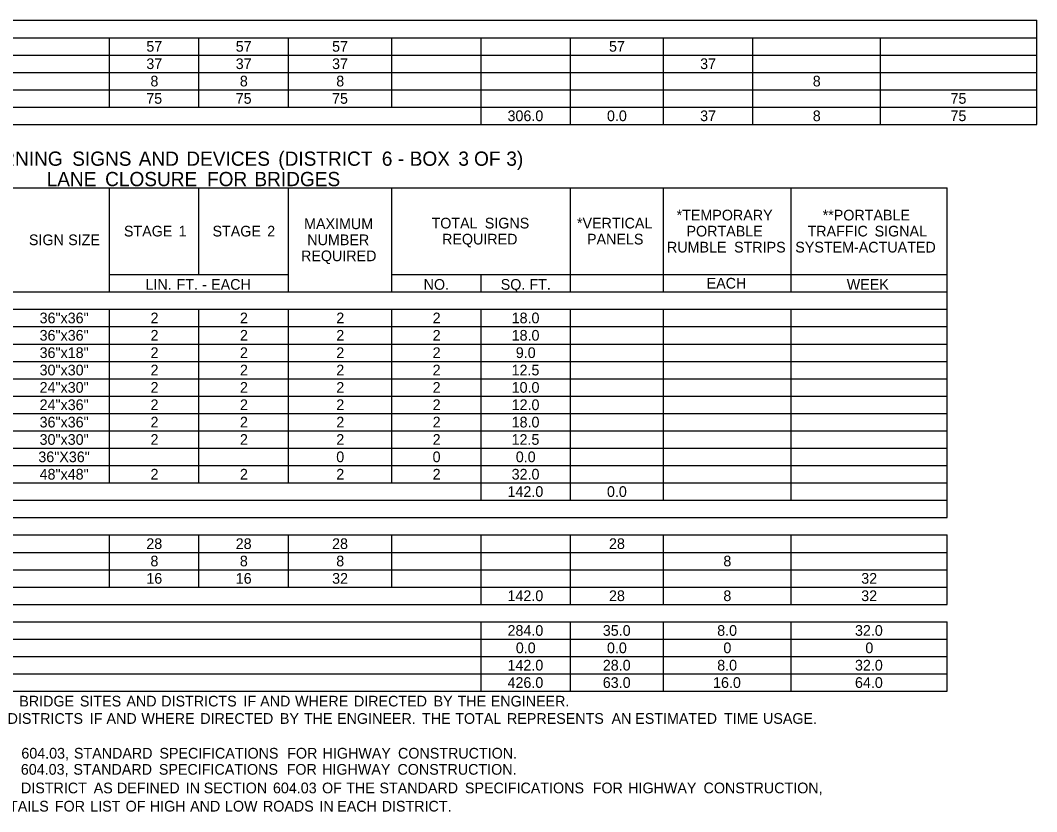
# Model space of a CAD drawing. Extents: x 542596 to 1930787, y -1948294 to 596640.
# Drawn here: x 542920 to 543491, y -1946974 to -1946530 of the extents above; entities that cross this region are included whole.
import ezdxf

# ---------------------------------------------------------------- set-up
doc = ezdxf.new("R2010")
doc.units = 0
doc.layers.add('Default', color=7, linetype='Continuous')

msp = doc.modelspace()

# ---------------------------------------------------------------- linework, layer by layer
at = {"layer": 'Default'}
for p, q in [((542602.25, -1946529.94), (543490.96, -1946529.94)), ((542652.46, -1946529.94), (543403.21, -1946529.94)), ((543403.21, -1946529.94), (543490.96, -1946529.94)), ((543490.96, -1946588.44), (543490.96, -1946529.94)), ((542602.25, -1946539.69), (543490.96, -1946539.69)), ((542970.31, -1946578.69), (542970.31, -1946539.69)), ((542970.31, -1946578.69), (542970.31, -1946539.69)), ((543020.52, -1946578.69), (543020.52, -1946539.69)), ((543020.52, -1946578.69), (543020.52, -1946539.69)), ((543070.73, -1946578.69), (543070.73, -1946539.69)), ((543070.73, -1946578.69), (543070.73, -1946539.69)), ((543128.75, -1946578.69), (543128.75, -1946539.69)), ((543178.96, -1946578.69), (543178.96, -1946539.69)), ((543178.96, -1946588.44), (543178.96, -1946539.69)), ((543229.17, -1946588.44), (543229.17, -1946539.69)), ((543229.17, -1946588.44), (543229.17, -1946539.69)), ((543281.33, -1946588.44), (543281.33, -1946539.69)), ((543281.33, -1946588.44), (543281.33, -1946539.69)), ((543331.55, -1946588.44), (543331.55, -1946539.69)), ((543331.55, -1946588.44), (543331.55, -1946539.69)), ((543403.21, -1946588.44), (543403.21, -1946539.69)), ((542602.25, -1946549.44), (543490.96, -1946549.44)), ((542602.25, -1946559.19), (543490.96, -1946559.19)), ((542602.25, -1946568.94), (543490.96, -1946568.94)), ((542602.25, -1946578.69), (543490.96, -1946578.69)), ((542920.1, -1946578.69), (543178.96, -1946578.69)), ((543403.21, -1946588.44), (543403.21, -1946578.69)), ((542602.25, -1946588.44), (543490.96, -1946588.44)), ((542602.25, -1946623.95), (543440.75, -1946623.95)), ((542970.31, -1946682.45), (542970.31, -1946623.95)), ((543020.52, -1946672.7), (543020.52, -1946623.95)), ((543070.73, -1946682.45), (543070.73, -1946623.95)), ((543128.75, -1946682.45), (543128.75, -1946623.95)), ((543229.17, -1946682.45), (543229.17, -1946623.95)), ((543281.33, -1946682.45), (543281.33, -1946623.95)), ((543353, -1946682.45), (543353, -1946623.95)), ((543440.75, -1946809.2), (543440.75, -1946623.95)), ((542970.31, -1946672.7), (543070.73, -1946672.7)), ((543070.73, -1946682.45), (543070.73, -1946672.7)), ((543128.75, -1946672.7), (543440.75, -1946672.7)), ((543178.96, -1946682.45), (543178.96, -1946672.7)), ((543229.17, -1946682.45), (543229.17, -1946672.7)), ((543281.33, -1946682.45), (543281.33, -1946672.7)), ((543353, -1946682.45), (543353, -1946672.7)), ((542602.25, -1946682.45), (543440.75, -1946682.45)), ((543070.73, -1946682.45), (543229.17, -1946682.45)), ((543229.17, -1946682.45), (543281.33, -1946682.45)), ((543281.33, -1946682.45), (543440.75, -1946682.45)), ((542602.25, -1946692.2), (543440.75, -1946692.2)), ((542970.31, -1946789.7), (542970.31, -1946692.2)), ((542970.31, -1946789.7), (542970.31, -1946692.2)), ((543020.52, -1946779.95), (543020.52, -1946692.2)), ((543020.52, -1946789.7), (543020.52, -1946692.2)), ((543070.73, -1946789.7), (543070.73, -1946692.2)), ((543070.73, -1946789.7), (543070.73, -1946692.2)), ((543128.75, -1946789.7), (543128.75, -1946692.2)), ((543178.96, -1946789.7), (543178.96, -1946692.2)), ((543178.96, -1946799.45), (543178.96, -1946692.2)), ((543229.17, -1946779.95), (543229.17, -1946692.2)), ((543229.17, -1946799.45), (543229.17, -1946692.2)), ((543281.33, -1946740.95), (543281.33, -1946692.2)), ((543281.33, -1946799.45), (543281.33, -1946692.2)), ((543353, -1946799.45), (543353, -1946692.2)), ((542602.25, -1946701.95), (543440.75, -1946701.95)), ((542602.25, -1946711.7), (543440.75, -1946711.7)), ((542602.25, -1946721.45), (543440.75, -1946721.45)), ((542602.25, -1946731.2), (543440.75, -1946731.2)), ((542602.25, -1946740.95), (543440.75, -1946740.95)), ((542602.25, -1946750.7), (543440.75, -1946750.7)), ((543281.33, -1946799.45), (543281.33, -1946750.7)), ((542602.25, -1946760.45), (543440.75, -1946760.45)), ((542602.25, -1946770.2), (543440.75, -1946770.2)), ((542602.25, -1946779.95), (543440.75, -1946779.95)), ((542602.25, -1946789.7), (543440.75, -1946789.7)), ((543178.96, -1946789.7), (543440.75, -1946789.7)), ((543353, -1946799.45), (543353, -1946789.7)), ((542602.25, -1946799.45), (543440.75, -1946799.45)), ((543353, -1946799.45), (543440.75, -1946799.45)), ((542602.25, -1946809.2), (543440.75, -1946809.2)), ((542652.46, -1946809.2), (543353, -1946809.2)), ((543353, -1946809.2), (543440.75, -1946809.2)), ((542602.25, -1946818.95), (543440.75, -1946818.95)), ((542970.31, -1946848.2), (542970.31, -1946818.95)), ((542970.31, -1946848.2), (542970.31, -1946818.95)), ((543020.52, -1946848.2), (543020.52, -1946818.95)), ((543020.52, -1946848.2), (543020.52, -1946818.95)), ((543070.73, -1946848.2), (543070.73, -1946818.95)), ((543070.73, -1946848.2), (543070.73, -1946818.95)), ((543128.75, -1946848.2), (543128.75, -1946818.95)), ((543178.96, -1946848.2), (543178.96, -1946818.95)), ((543178.96, -1946857.95), (543178.96, -1946818.95)), ((543229.17, -1946857.95), (543229.17, -1946818.95)), ((543229.17, -1946857.95), (543229.17, -1946818.95)), ((543281.33, -1946857.95), (543281.33, -1946818.95)), ((543281.33, -1946857.95), (543281.33, -1946818.95)), ((543353, -1946857.95), (543353, -1946818.95)), ((543440.75, -1946857.95), (543440.75, -1946818.95)), ((542602.25, -1946828.7), (543440.75, -1946828.7)), ((543353, -1946838.45), (543353, -1946828.7)), ((542602.25, -1946838.45), (543440.75, -1946838.45)), ((542602.25, -1946848.2), (543440.75, -1946848.2)), ((542602.25, -1946848.2), (543440.75, -1946848.2)), ((543353, -1946857.95), (543353, -1946848.2)), ((542602.25, -1946857.95), (543440.75, -1946857.95)), ((542602.25, -1946867.7), (543440.75, -1946867.7)), ((543178.96, -1946906.7), (543178.96, -1946867.7)), ((543178.96, -1946906.7), (543178.96, -1946867.7)), ((543229.17, -1946906.7), (543229.17, -1946867.7)), ((543281.33, -1946906.7), (543281.33, -1946867.7)), ((543353, -1946906.7), (543353, -1946867.7)), ((543440.75, -1946906.7), (543440.75, -1946867.7)), ((542602.25, -1946877.45), (543440.75, -1946877.45)), ((542602.25, -1946887.2), (543440.75, -1946887.2)), ((542602.25, -1946896.95), (543440.75, -1946896.95)), ((542602.25, -1946906.7), (543440.75, -1946906.7))]:
    msp.add_line(p, q, dxfattribs=at)

# ---------------------------------------------------------------- texts
for s, height, p in [('57', 6, (542990.95, -1946547.56)), ('57', 6, (543041.16, -1946547.56)), ('57', 6, (543095.27, -1946547.56)), ('57', 6, (543250.78, -1946547.56)), ('37', 6, (542990.95, -1946557.31)), ('37', 6, (543041.16, -1946557.31)), ('37', 6, (543095.27, -1946557.31)), ('37', 6, (543301.97, -1946557.31)), ('8', 6, (542993.27, -1946567.06)), ('8', 6, (543043.48, -1946567.06)), ('8', 6, (543097.6, -1946567.06)), ('8', 6, (543365.23, -1946567.06)), ('75', 6, (542990.92, -1946576.81)), ('75', 6, (543041.14, -1946576.81)), ('75', 6, (543095.25, -1946576.81)), ('75', 6, (543442.59, -1946576.81)), ('306.0', 6, (543193.79, -1946586.56)), ('0.0', 6, (543249.64, -1946586.56)), ('37', 6, (543301.97, -1946586.56)), ('8', 6, (543365.24, -1946586.56)), ('75', 6, (543442.55, -1946586.56)), (' WARNING', 8, (542889.27, -1946611.62)), (' SIGNS', 8, (542946.34, -1946611.62)), (' AND', 8, (542983.68, -1946611.62)), (' DEVICES', 8, (543010.45, -1946611.62)), (' (DISTRICT', 8, (543062.08, -1946611.62)), (' 6', 8, (543120.22, -1946611.62)), (' -', 8, (543129.14, -1946611.62)), (' BOX', 8, (543135.88, -1946611.62)), (' 3', 8, (543163.2, -1946611.62)), (' OF', 8, (543172.03, -1946611.62)), (' 3)', 8, (543190.14, -1946611.62)), ('LANE', 8, (542934.96, -1946623.07)), (' CLOSURE', 8, (542964.84, -1946623.07)), (' FOR', 8, (543022.05, -1946623.07)), (' BRIDGES', 8, (543048.69, -1946623.07)), ('*TEMPORARY', 6, (543288.74, -1946642.32)), ('**PORTABLE', 6, (543370.76, -1946642.32)), ('MAXIMUM', 6, (543079.55, -1946647.2)), ('TOTAL', 6, (543151.11, -1946646.82)), (' SIGNS', 6, (543178.8, -1946646.82)), ('*VERTICAL', 6, (543232.79, -1946646.82)), ('STAGE', 6, (542978.37, -1946651.32)), (' 1', 6, (543006.84, -1946651.32)), ('STAGE', 6, (543028.11, -1946651.32)), (' 2', 6, (543056.58, -1946651.32)), ('PORTABLE', 6, (543294.32, -1946651.32)), ('TRAFFIC', 6, (543362.28, -1946651.32)), (' SIGNAL', 6, (543397.71, -1946651.32)), ('SIGN', 6, (542925.02, -1946656.2)), (' SIZE', 6, (542944.84, -1946656.2)), ('NUMBER', 6, (543081.36, -1946656.2)), ('REQUIRED', 6, (543157.04, -1946655.82)), ('PANELS', 6, (543238.45, -1946655.82)), ('REQUIRED', 6, (543077.82, -1946665.2)), ('RUMBLE', 6, (543283.34, -1946660.32)), (' STRIPS', 6, (543318.79, -1946660.32)), ('SYSTEM-ACTUATED', 6, (543355.39, -1946660.32)), ('LIN.', 6, (542990.48, -1946681.25)), (' FT.', 6, (543005.74, -1946681.25)), (' EACH', 6, (543025.12, -1946681.25)), ('NO.', 6, (543146.69, -1946681.25)), ('SQ.', 6, (543189.97, -1946681.25)), (' FT.', 6, (543203.84, -1946681.25)), ('EACH', 6, (543305.61, -1946680.57)), ('WEEK', 6, (543384.3, -1946681.25)), (' -', 6, (543020.06, -1946681.25)), ('36"x36"', 6, (542931.01, -1946700.07)), ('2', 6, (542993.31, -1946700.07)), ('2', 6, (543043.52, -1946700.07)), ('2', 6, (543097.63, -1946700.07)), ('2', 6, (543151.75, -1946700.07)), ('18.0', 6, (543196.11, -1946700.07)), ('36"x36"', 6, (542931.01, -1946709.82)), ('2', 6, (542993.31, -1946709.82)), ('2', 6, (543043.52, -1946709.82)), ('2', 6, (543097.63, -1946709.82)), ('2', 6, (543151.75, -1946709.82)), ('18.0', 6, (543196.11, -1946709.82)), ('36"x18"', 6, (542931.01, -1946719.57)), ('2', 6, (542993.31, -1946719.57)), ('2', 6, (543043.52, -1946719.57)), ('2', 6, (543097.63, -1946719.57)), ('2', 6, (543151.75, -1946719.57)), ('9.0', 6, (543198.44, -1946719.57)), ('30"x30"', 6, (542931.01, -1946729.32)), ('2', 6, (542993.31, -1946729.32)), ('2', 6, (543043.52, -1946729.32)), ('2', 6, (543097.63, -1946729.32)), ('2', 6, (543151.75, -1946729.32)), ('12.5', 6, (543196.08, -1946729.32)), ('24"x30"', 6, (542931.01, -1946739.07)), ('2', 6, (542993.31, -1946739.07)), ('2', 6, (543043.52, -1946739.07)), ('2', 6, (543097.63, -1946739.07)), ('2', 6, (543151.75, -1946739.07)), ('10.0', 6, (543196.11, -1946739.07)), ('24"x36"', 6, (542931.01, -1946748.82)), ('2', 6, (542993.31, -1946748.82)), ('2', 6, (543043.52, -1946748.82)), ('2', 6, (543097.63, -1946748.82)), ('2', 6, (543151.75, -1946748.82)), ('12.0', 6, (543196.11, -1946748.82)), ('36"x36"', 6, (542931.01, -1946758.57)), ('2', 6, (542993.31, -1946758.57)), ('2', 6, (543043.52, -1946758.57)), ('2', 6, (543097.63, -1946758.57)), ('2', 6, (543151.75, -1946758.57)), ('18.0', 6, (543196.11, -1946758.57)), ('30"x30"', 6, (542931.01, -1946768.32)), ('2', 6, (542993.31, -1946768.32)), ('2', 6, (543043.52, -1946768.32)), ('2', 6, (543097.63, -1946768.32)), ('2', 6, (543151.75, -1946768.32)), ('12.5', 6, (543196.08, -1946768.32)), ('36"X36"', 6, (542930.31, -1946778.07)), ('0', 6, (543097.61, -1946778.07)), ('0', 6, (543151.72, -1946778.07)), ('0.0', 6, (543198.44, -1946778.07)), ('48"x48"', 6, (542931.01, -1946787.82)), ('2', 6, (542993.31, -1946787.82)), ('2', 6, (543043.52, -1946787.82)), ('2', 6, (543097.63, -1946787.82)), ('2', 6, (543151.75, -1946787.82)), ('32.0', 6, (543196.11, -1946787.82)), ('142.0', 6, (543193.79, -1946797.57)), ('0.0', 6, (543249.64, -1946797.57)), ('28', 6, (542990.94, -1946826.82)), ('28', 6, (543041.15, -1946826.82)), ('28', 6, (543095.27, -1946826.82)), ('28', 6, (543250.78, -1946826.82)), ('8', 6, (542993.27, -1946836.57)), ('8', 6, (543043.48, -1946836.57)), ('8', 6, (543097.6, -1946836.57)), ('8', 6, (543315.02, -1946836.57)), ('16', 6, (542990.95, -1946846.32)), ('16', 6, (543041.16, -1946846.32)), ('32', 6, (543095.3, -1946846.32)), ('32', 6, (543392.43, -1946846.32)), ('142.0', 6, (543193.79, -1946856.07)), ('28', 6, (543250.78, -1946856.07)), ('8', 6, (543315.02, -1946856.07)), ('32', 6, (543392.42, -1946856.07)), ('284.0', 6, (543193.79, -1946875.57)), ('35.0', 6, (543247.31, -1946875.57)), ('8.0', 6, (543311.55, -1946875.57)), ('32.0', 6, (543388.92, -1946875.57)), ('0.0', 6, (543198.45, -1946885.32)), ('0.0', 6, (543249.64, -1946885.32)), ('0', 6, (543315.04, -1946885.32)), ('0', 6, (543394.75, -1946885.32)), ('142.0', 6, (543193.79, -1946895.07)), ('28.0', 6, (543247.31, -1946895.07)), ('8.0', 6, (543311.55, -1946895.07)), ('32.0', 6, (543388.92, -1946895.07)), ('426.0', 6, (543193.79, -1946904.82)), ('63.0', 6, (543247.31, -1946904.82)), ('16.0', 6, (543309.22, -1946904.82)), ('64.0', 6, (543388.92, -1946904.82)), (' BRIDGE', 6, (542917.39, -1946915.25)), (' SITES', 6, (542951.41, -1946915.25)), (' AND', 6, (542977.53, -1946915.25)), (' DISTRICTS', 6, (542997.11, -1946915.25)), (' IF', 6, (543043.25, -1946915.25)), (' AND', 6, (543052.65, -1946915.25)), (' WHERE', 6, (543072.23, -1946915.25)), (' DIRECTED', 6, (543105.32, -1946915.25)), (' BY', 6, (543150.05, -1946915.25)), (' THE', 6, (543163.5, -1946915.25)), (' ENGINEER.', 6, (543182.15, -1946915.25)), (' DISTRICTS', 6, (542910.81, -1946925)), (' IF', 6, (542956.95, -1946925)), (' AND', 6, (542966.35, -1946925)), (' WHERE', 6, (542985.93, -1946925)), (' DIRECTED', 6, (543019.01, -1946925)), (' BY', 6, (543063.75, -1946925)), (' THE', 6, (543077.2, -1946925)), (' ENGINEER.', 6, (543095.85, -1946925)), (' THE', 6, (543143.57, -1946925)), (' TOTAL', 6, (543162.21, -1946925)), (' REPRESENTS', 6, (543191.26, -1946925)), (' AN', 6, (543250, -1946925)), (' ESTIMATED', 6, (543263.29, -1946925)), (' TIME', 6, (543313.15, -1946925)), (' USAGE.', 6, (543335.05, -1946925)), (' 604.03,', 6, (542918.53, -1946944.5)), (' STANDARD', 6, (542948.07, -1946944.5)), (' SPECIFICATIONS', 6, (542996.07, -1946944.5)), (' FOR', 6, (543067.83, -1946944.5)), (' HIGHWAY', 6, (543087.74, -1946944.5)), (' CONSTRUCTION.', 6, (543130.07, -1946944.5)), (' 604.03,', 6, (542918.24, -1946953.57)), (' STANDARD', 6, (542947.77, -1946953.57)), (' SPECIFICATIONS', 6, (542995.77, -1946953.57)), (' FOR', 6, (543067.54, -1946953.57)), (' HIGHWAY', 6, (543087.45, -1946953.57)), (' CONSTRUCTION.', 6, (543129.77, -1946953.57)), (' DISTRICT', 6, (542918.33, -1946964)), (' AS', 6, (542959.15, -1946964)), (' DEFINED', 6, (542972.22, -1946964)), (' IN', 6, (543010.9, -1946964)), (' SECTION', 6, (543020.93, -1946964)), (' 604.03', 6, (543059.83, -1946964)), (' OF', 6, (543087.41, -1946964)), (' THE', 6, (543101, -1946964)), (' STANDARD', 6, (543119.65, -1946964)), (' SPECIFICATIONS', 6, (543167.65, -1946964)), (' FOR', 6, (543239.41, -1946964)), (' HIGHWAY', 6, (543259.33, -1946964)), (' CONSTRUCTION,', 6, (543301.65, -1946964)), (' DETAILS', 6, (542900.5, -1946974.24)), (' FOR', 6, (542937.33, -1946974.24)), (' LIST', 6, (542957.24, -1946974.24)), (' OF', 6, (542977.11, -1946974.24)), (' HIGH', 6, (542990.69, -1946974.24)), (' AND', 6, (543013.3, -1946974.24)), (' LOW', 6, (543032.89, -1946974.24)), (' ROADS', 6, (543054.21, -1946974.24)), (' IN', 6, (543085.92, -1946974.24)), (' EACH', 6, (543095.94, -1946974.24)), (' DISTRICT.', 6, (543120.89, -1946974.24))]:
    msp.add_text(s, height=height, dxfattribs=at).set_placement(p)

doc.saveas('drawing.dxf')
